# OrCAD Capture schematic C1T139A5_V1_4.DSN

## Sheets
1 00_Log: title: Telink-Semi; rev: V1.4; note: C1T139A5
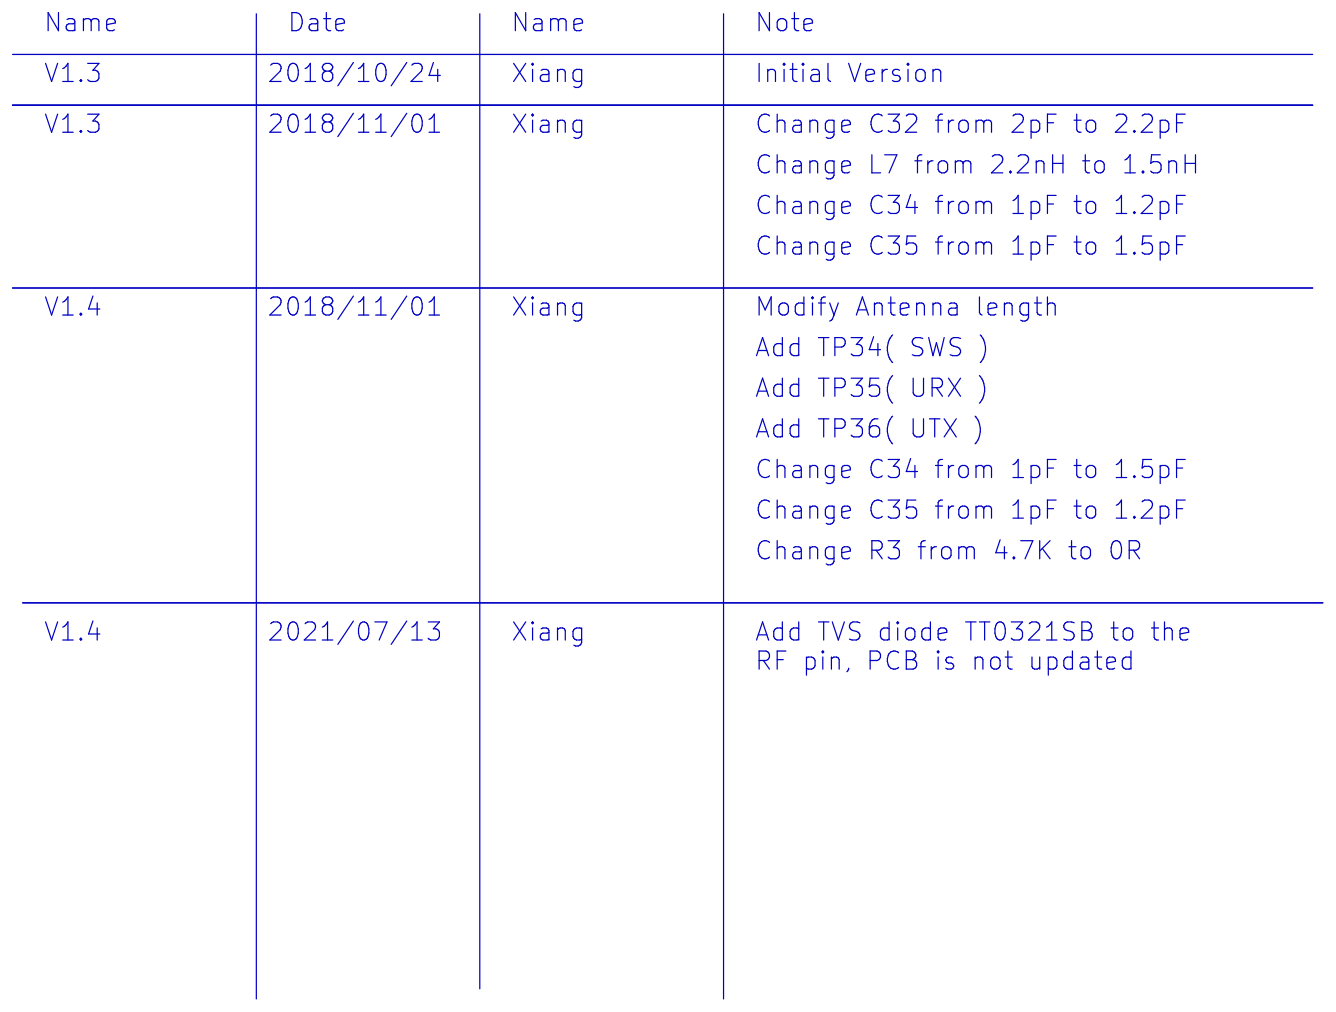
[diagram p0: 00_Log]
2 05_IR: size A4
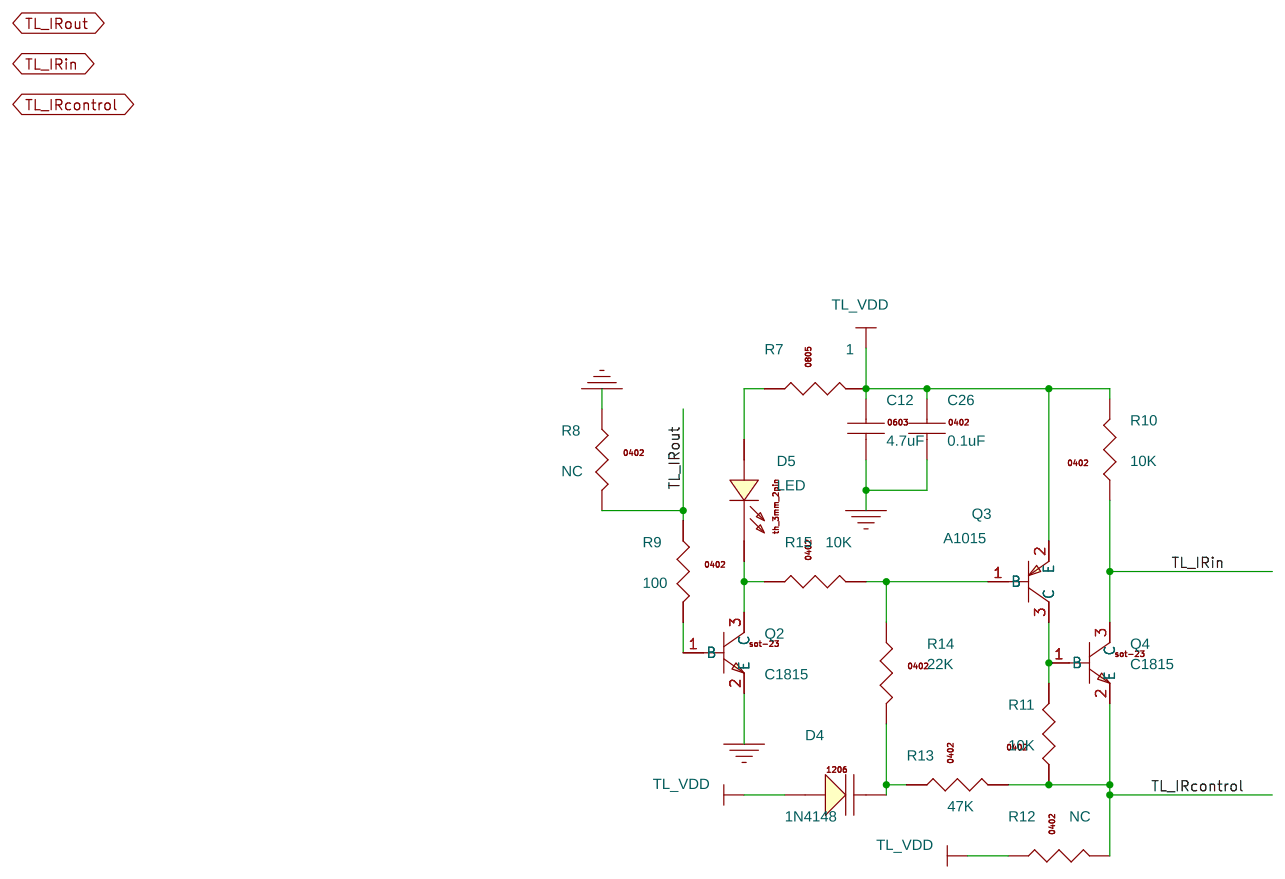
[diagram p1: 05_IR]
3 04_Audio: size A4
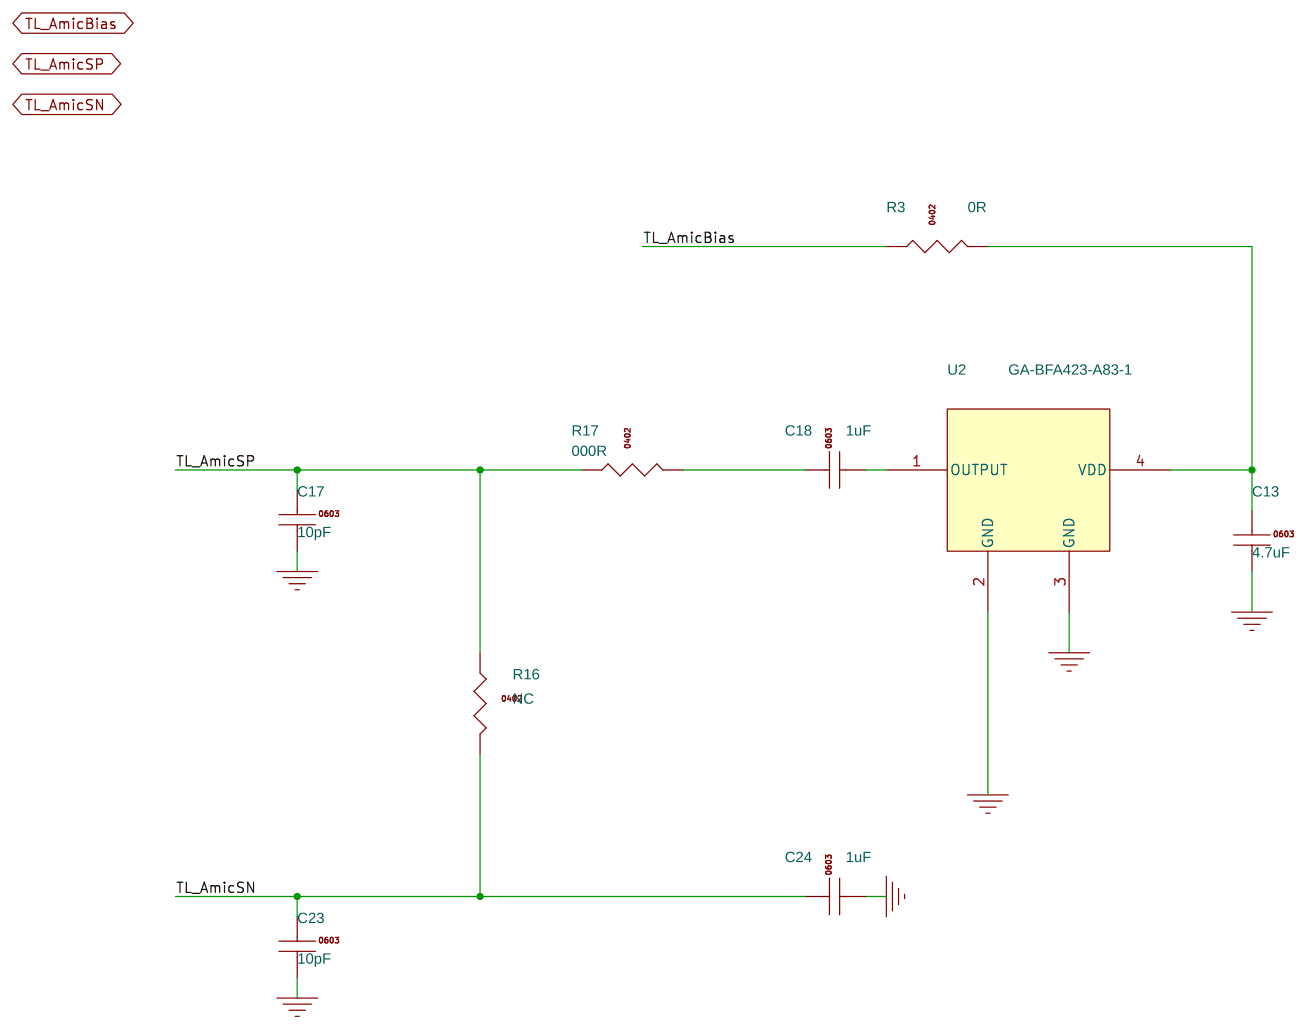
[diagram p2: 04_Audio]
4 01_CPU: size A4
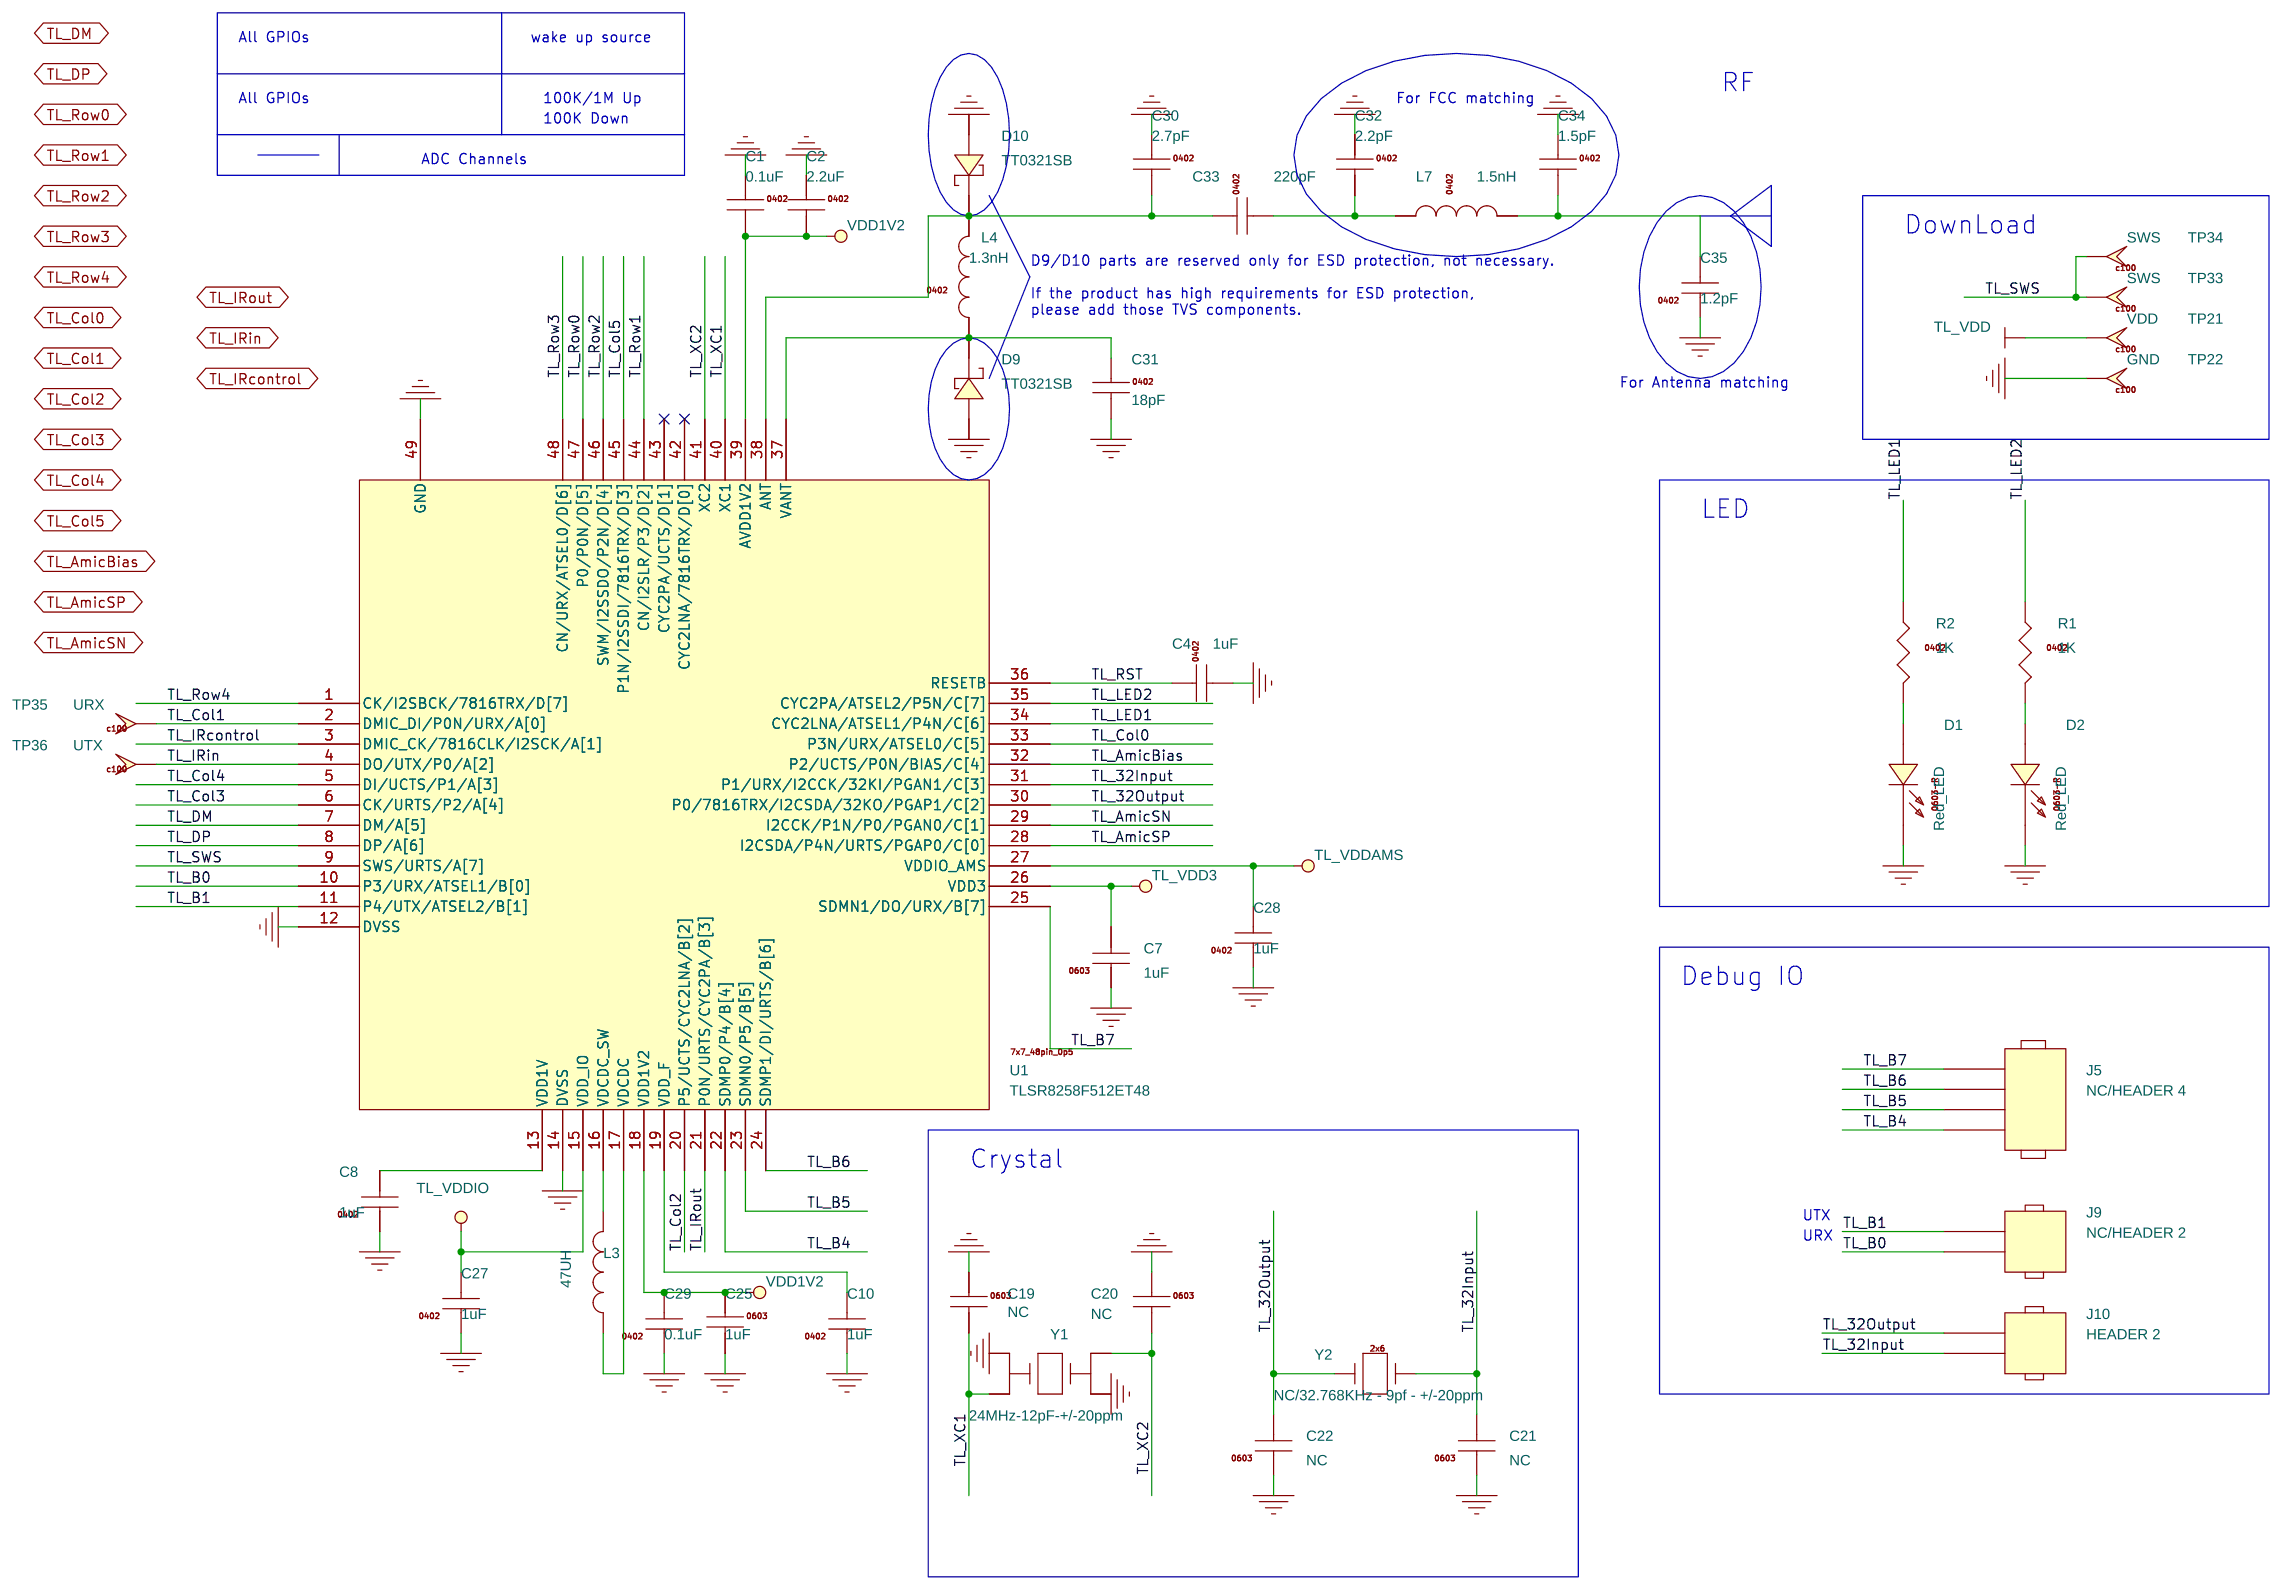
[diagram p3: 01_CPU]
5 02_Key: size A4
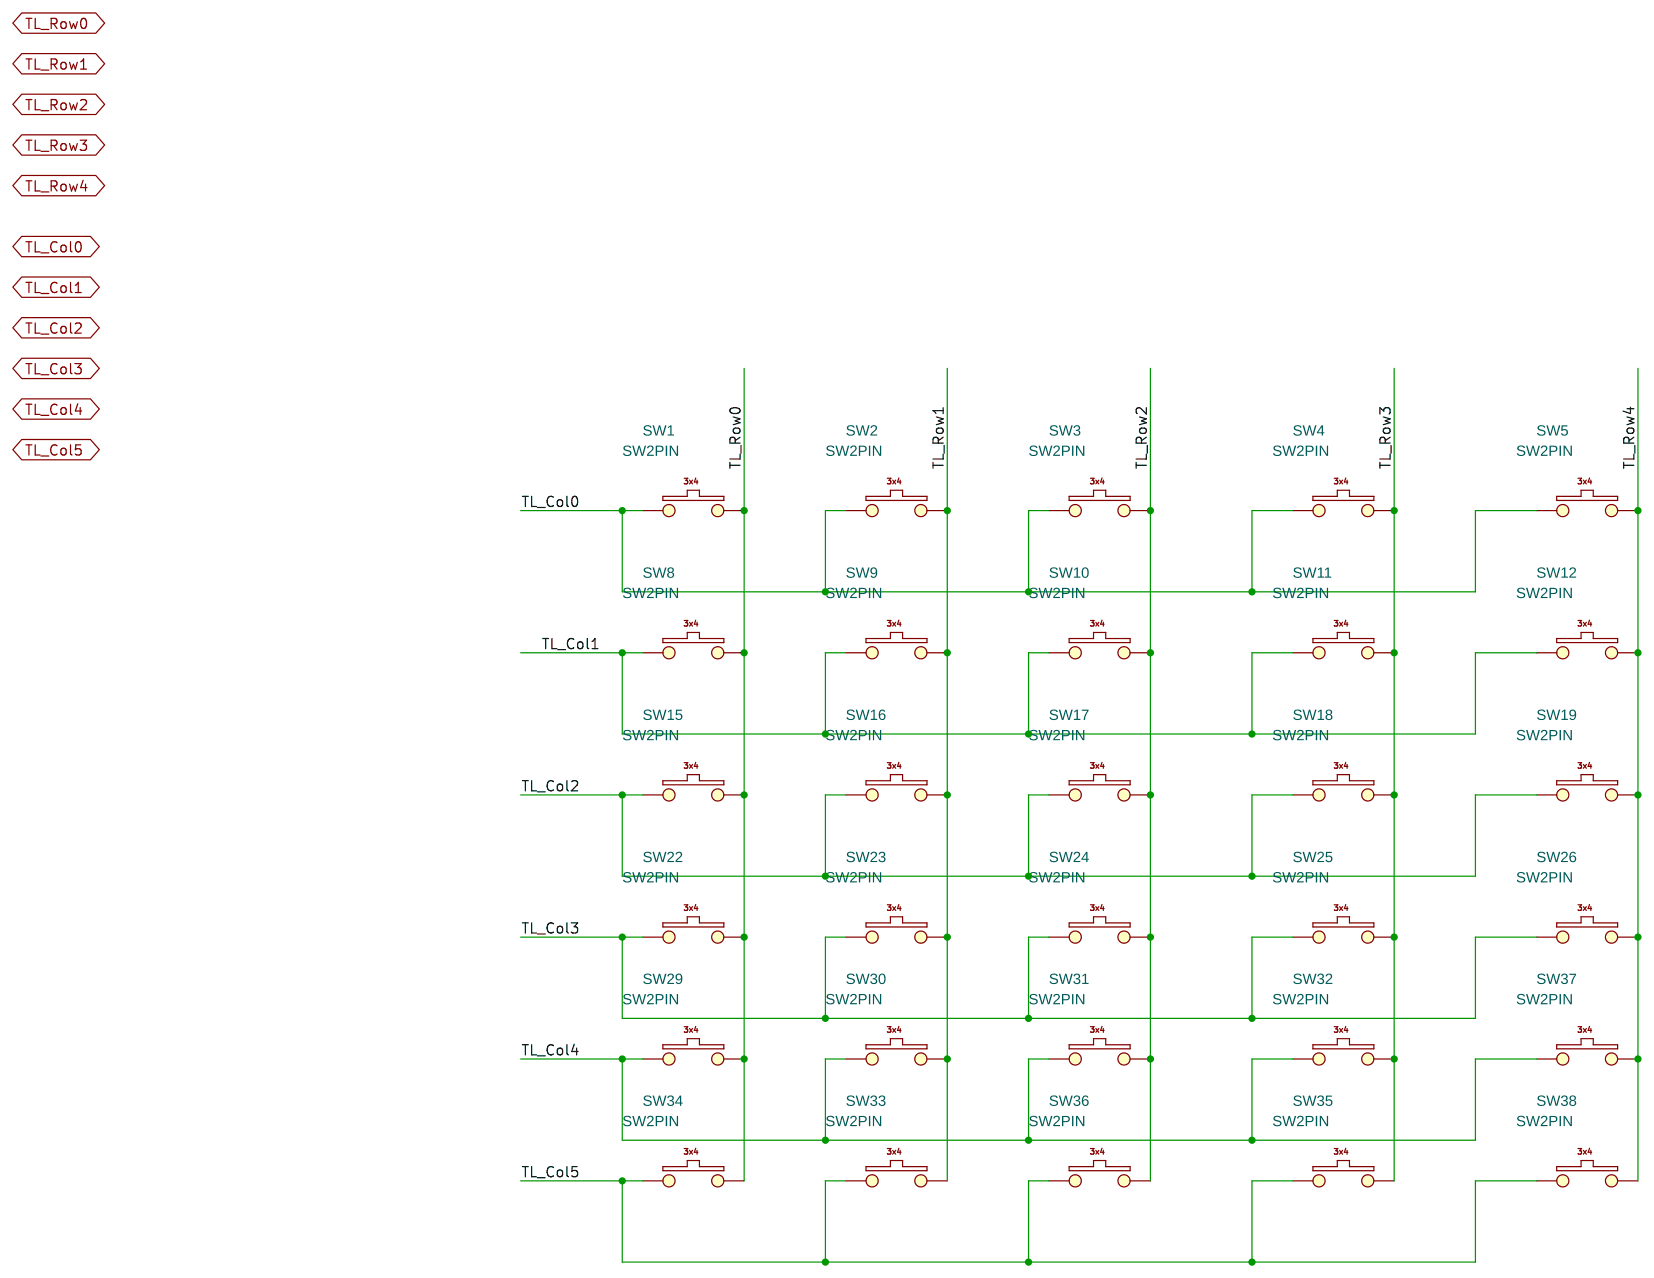
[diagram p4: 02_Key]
6 03_Power: size A4
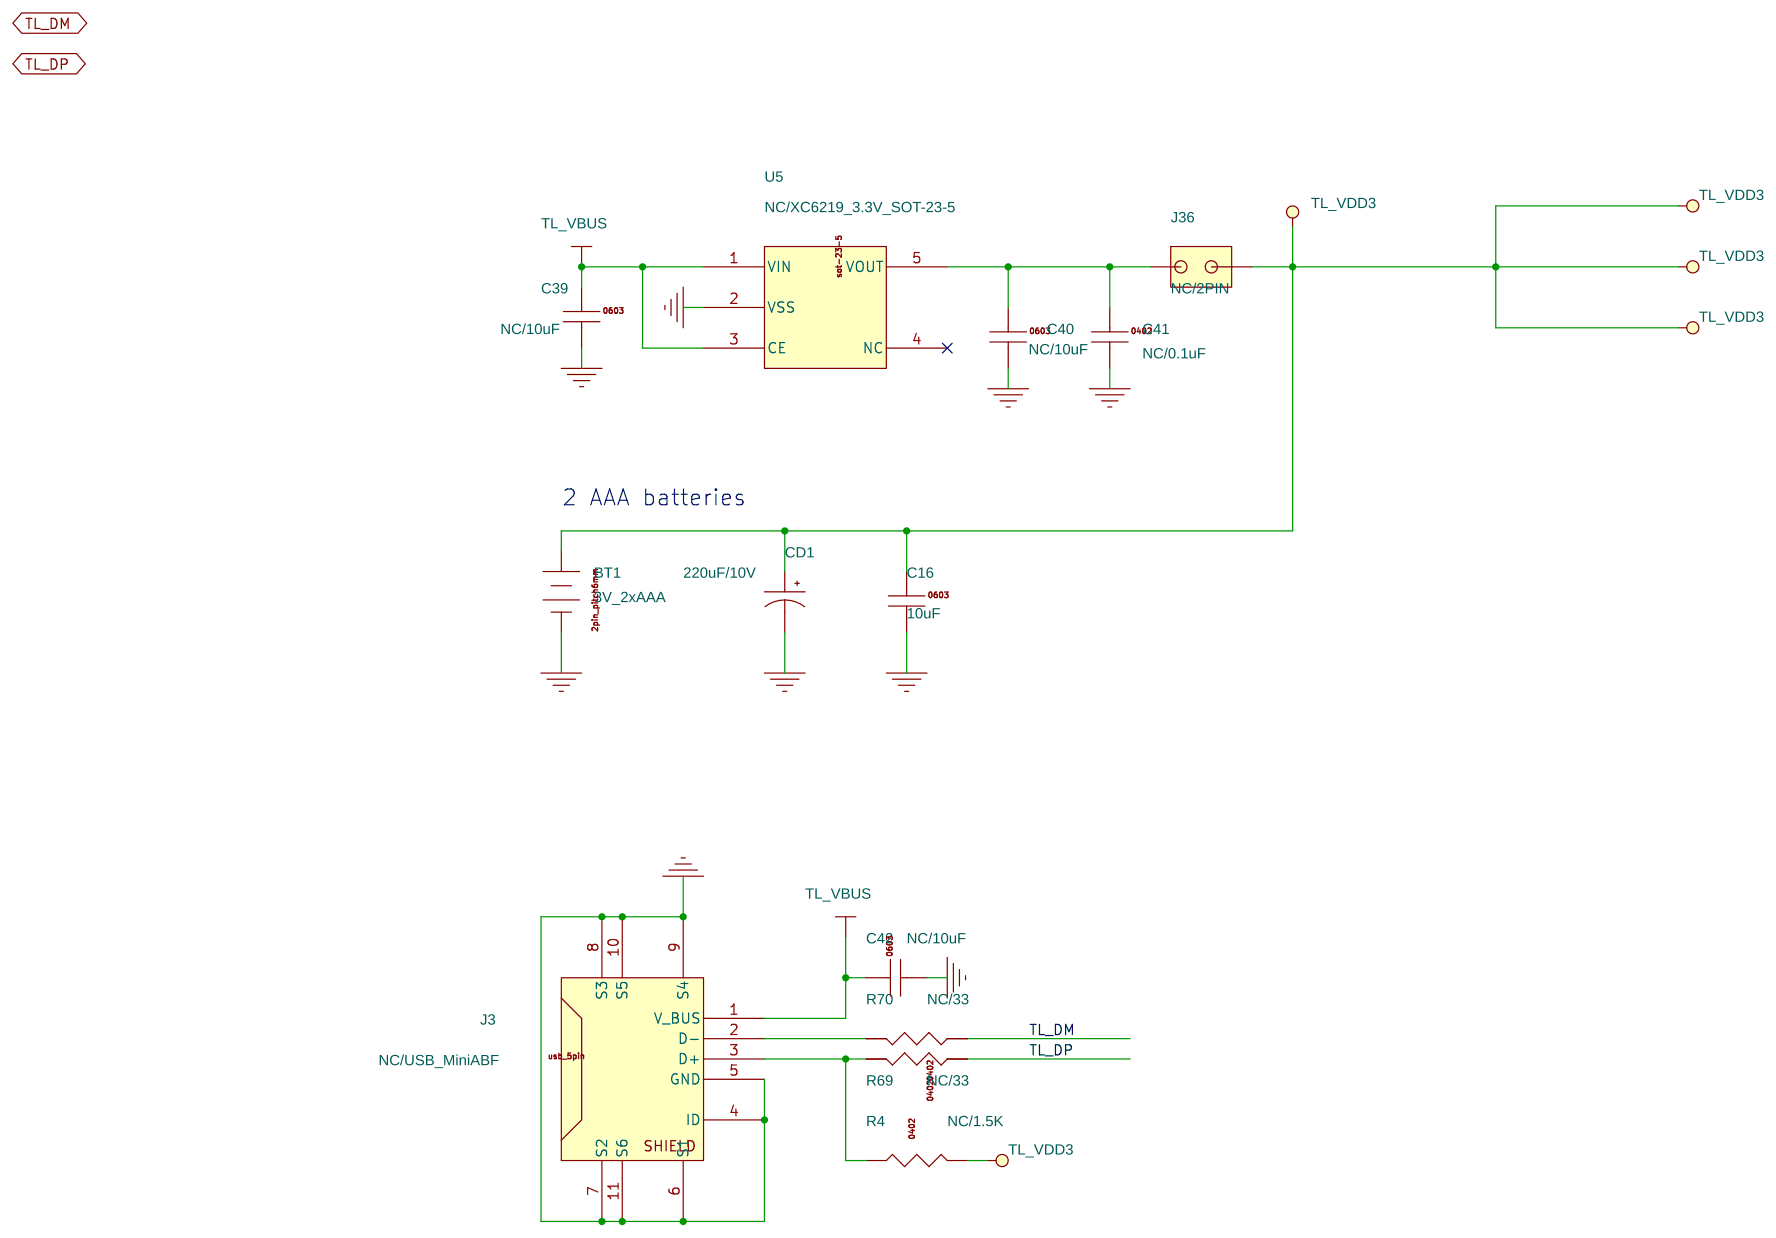
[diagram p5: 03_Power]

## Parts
sheet 01_CPU
C1  0.1uF  [0402]
C2  2.2uF  [0402]
C4  1uF  [0402]
C7  1uF  [0402]
C8  1uF  [0402]
C10  1uF  [0402]
C19  NC  [0402]
C20  NC  [0402]
C21  NC  [0402]
C22  NC  [0402]
C25  1uF  [0402]
C27  1uF  [0402]
C28  1uF  [0402]
C29  0.1uF  [0402]
C30  2.7pF  [0402C]
C31  18pF  [0402]
C32  2.2pF  [0402C]
C33  220pF  [0402C]
C34  1.5pF  [0402C]
C35  1.2pF  [0402]
D1  Red_LED  [0603-LED]
D2  Red_LED  [0603-LED]
D9  TT0321SB  [SOD-123]
D10  TT0321SB  [SOD-123]
J5  NC/HEADER 4  [hdr254f-1x4x850]
J9  NC/HEADER 2  [hdr254f-1x2x850]
J10  HEADER 2  [hdr254f-1x2x850]
L3  47UH  [0805L]
L4  1.3nH  [0402C]
L7  1.5nH  [0402C]
R1  1K  [0402]
R2  1K  [0402]
TP21  VDD  [tp100]
TP22  GND  [tp100]
TP33  SWS  [tp100]
TP34  SWS  [tp100]
TP35  URX  [tp100]
TP36  UTX  [tp100]
U1  TLSR8258F512ET48  [qfn_7x7_48pin_0p5_4p20x4p20]
Y1  24MHz-12pF-+/-20ppm  [osccc250x320x110]
Y2  NC/32.768KHz - 9pf - +/-20ppm  [OSC_2x6]
sheet 02_Key
SW1  SW2PIN  [sw_out6_in3]
SW2  SW2PIN  [sw_out6_in3]
SW3  SW2PIN  [sw_out6_in3]
SW4  SW2PIN  [sw_out6_in3]
SW5  SW2PIN  [sw_out6_in3]
SW8  SW2PIN  [sw_out6_in3]
SW9  SW2PIN  [sw_out6_in3]
SW10  SW2PIN  [sw_out6_in3]
SW11  SW2PIN  [sw_out6_in3]
SW12  SW2PIN  [sw_out6_in3]
SW15  SW2PIN  [sw_out6_in3]
SW16  SW2PIN  [sw_out6_in3]
SW17  SW2PIN  [sw_out6_in3]
SW18  SW2PIN  [sw_out6_in3]
SW19  SW2PIN  [sw_out6_in3]
SW22  SW2PIN  [sw_out6_in3]
SW23  SW2PIN  [sw_out6_in3]
SW24  SW2PIN  [sw_out6_in3]
SW25  SW2PIN  [sw_out6_in3]
SW26  SW2PIN  [sw_out6_in3]
SW29  SW2PIN  [sw_out6_in3]
SW30  SW2PIN  [sw_out6_in3]
SW31  SW2PIN  [sw_out6_in3]
SW32  SW2PIN  [sw_out6_in3]
SW33  SW2PIN  [sw_out6_in3]
SW34  SW2PIN  [sw_out6_in3]
SW35  SW2PIN  [sw_out6_in3]
SW36  SW2PIN  [sw_out6_in3]
SW37  SW2PIN  [sw_out6_in3]
SW38  SW2PIN  [sw_out6_in3]
sheet 03_Power
BT1  3V_2xAAA  [bat_2dip]
C16  10uF  [0603c]
C39  NC/10uF  [0603c]
C40  NC/10uF  [0603c]
C41  NC/0.1uF  [0402]
C42  NC/10uF  [0603c]
CD1  220uF/10V  [cd2p0_4p0b]
J3  NC/USB_MiniABF  [microusb_dip]
J36  NC/2PIN  [HDR254F-1X2X850]
R4  NC/1.5K  [0402]
R69  NC/33  [0402]
R70  NC/33  [0402]
U5  NC/XC6219_3.3V_SOT-23-5  [sot-23-5]
sheet 04_Audio
C13  4.7uF  [0402]
C17  10pF  [0402]
C18  1uF  [0402]
C23  10pF  [0402]
C24  1uF  [0402]
R3  0R  [0402]
R16  NC  [0402]
R17  000R  [0402]
U2  GA-BFA423-A83-1  [ga_bfa423_a83]
sheet 05_IR
C12  4.7uF  [0402]
C26  0.1uF  [0402]
D4  1N4148  [SOD80]
D5  LED  [led_th_2p54mm_2pin]
Q2  C1815  [SOT-23]
Q3  A1015  [SOT-23]
Q4  C1815  [SOT-23]
R7  1  [0402]
R8  NC  [0402]
R9  100  [0402]
R10  10K  [0402]
R11  10K  [0402]
R12  NC  [0402]
R13  47K  [0402]
R14  22K  [0402]
R15  10K  [0402]

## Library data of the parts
C1 C26 C41 = C1005X5R1C104K
C2 = C1005X5R1A225K
C4 C8 = C1005X5R1C105K
C7 = C1608X5R1C105M_0
C10 = C1005X5R1C105K_0
C19-C22 = C1608_NC
C13 C17 C18 C23-C25 = C1608X5R0J475M
C27 C29 = C1005X5R1C105K_1
C28 = C1005X5R1C105K_2
C30 C32-C34 = C1608_NC_0
C31 = C1005C0G1H100D
C35 = C1005_NC
D1 D2 = 0603D_Red
D9 D10 = DIODE_SCHOTTKY_0
J5 = HEADER_4
J9 J10 = HEADER_2
L3 = IND_0
L4 L7 = MLK1608_0
R1-R4 R16 R17 = RS0402K472JT
TP21 TP22 TP33-TP36 = TestPad100
U1 = TLSR8258F512ET48
Y1 = CRYSTAL4_SM_0
Y2 = OSC_2x6_2pin_16Mhz
SW1-SW5 SW8-SW12 SW15-SW19 SW22-SW26 SW29-SW38 = SW2PIN_0
BT1 = BATTERY_2xAAA_3V
C16 = C1608X5R0J106M
C39 C40 C42 = C1608X5R1A106K
CD1 = CD_220uF_16V
J3 = USB_MiniABF_2
J36 = B2S_2: PAGE: POWER
R69 R70 = RS0402K330JT
U5 = XC6219_1.3V_SOT-23-5
U2 = MULPS4CX-RM5_0
C12 = C1608X5R1A226M
D4 = Diode_1N4148
D5 = Led_Th_3mm_1
Q2 Q4 = NPN_C1815
Q3 = PNP_A1015
R7 = RS0805K1R0JT
R8 R12 = RS0402_NC
R9 = RS0402K101JT
R10 R11 R15 = RS0402K103JT
R13 = RS0402K473JT
R14 = RS0402K223JT

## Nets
GND: BT1.2(-) C1.1 C2.1 C4.2 C7.1 C8.1 C10.1 C12.2 C13.2 C16.2 C17.2 C19.1 C20.1 C21.1 C22.1 C23.2 C24.2 C25.2 C26.2 C27.1 C28.1 C29.1 C30.1 C31.2 C32.1 C34.1 C35.1 C39.2 C40.2 C41.2 C42.2 CD1.2 D1.C(CATHODE) D2.C(CATHODE) D9.A(ANODE) D10.A(ANODE) J3.4(ID) J3.5(GND) J3.6(S1) J3.7(S2) J3.8(S3) J3.9(S4) J3.10(S5) J3.11(S6) Q2.2(E) R8.1 TP22.1(TP) U1.12(DVSS) U1.14(DVSS) U1.49(GND) U2.2(GND) U2.3(GND) U5.2(VSS) Y1.2 Y1.4
VDD1V2: C1.2 C2.2 C25.1 C29.2 U1.18(VDD1V2) U1.39(AVDD1V2)
TL_32Input: C21.2 J10.2 U1.31(P1/URX/I2CCK/32KI/PGAN1/C[3]) Y2.2
TL_32Output: C22.2 J10.1 U1.30(P0/7816TRX/I2CSDA/32KO/PGAP1/C[2]) Y2.1
TL_AmicBias: U1.32(P2/UCTS/P0N/BIAS/C[4])
TL_AmicBias (page 04_Audio): R3.1
TL_AmicSN: U1.29(I2CCK/P1N/P0/PGAN0/C[1])
TL_AmicSN (page 04_Audio): C23.1 C24.1 R16.2
TL_AmicSP: U1.28(I2CSDA/P4N/URTS/PGAP0/C[0])
TL_AmicSP (page 04_Audio): C17.1 R16.1 R17.1
TL_B0: J9.2 U1.10(P3/URX/ATSEL1/B[0])
TL_B1: J9.1 U1.11(P4/UTX/ATSEL2/B[1])
TL_B4: J5.1 U1.22(SDMP0/P4/B[4])
TL_B5: J5.2 U1.23(SDMN0/P5/B[5])
TL_B6: J5.3 U1.24(SDMP1/DI/URTS/B[6])
TL_B7: J5.4 U1.25(SDMN1/DO/URX/B[7])
TL_Col0: U1.33(P3N/URX/ATSEL0/C[5])
TL_Col0 (page 02_Key): SW1.1 SW2.1 SW3.1 SW4.1 SW5.1
TL_Col1: TP35.1(TP) U1.2(DMIC_DI/P0N/URX/A[0])
TL_Col1 (page 02_Key): SW8.1 SW9.1 SW10.1 SW11.1 SW12.1
TL_Col2: U1.20(P5/UCTS/CYC2LNA/B[2])
TL_Col2 (page 02_Key): SW15.1 SW16.1 SW17.1 SW18.1 SW19.1
TL_Col3: U1.6(CK/URTS/P2/A[4])
TL_Col3 (page 02_Key): SW22.1 SW23.1 SW24.1 SW25.1 SW26.1
TL_Col4: U1.5(DI/UCTS/P1/A[3])
TL_Col4 (page 02_Key): SW29.1 SW30.1 SW31.1 SW32.1 SW37.1
TL_Col5: U1.45(P1N/I2SSDI/7816TRX/D[3])
TL_Col5 (page 02_Key): SW33.1 SW34.1 SW35.1 SW36.1 SW38.1
TL_DM: U1.7(DM/A[5])
TL_DM (page 03_Power): R70.1
TL_DP: U1.8(DP/A[6])
TL_DP (page 03_Power): R69.1
TL_IRcontrol: U1.3(DMIC_CK/7816CLK/I2SCK/A[1])
TL_IRcontrol (page 05_IR): Q4.2(E) R11.1 R12.2 R13.2
TL_IRin: TP36.1(TP) U1.4(DO/UTX/P0/A[2])
TL_IRin (page 05_IR): Q4.3(C) R10.1
TL_IRout: U1.21(P0N/URTS/CYC2PA/B[3])
TL_IRout (page 05_IR): R8.2 R9.1
TL_LED1: R2.1 U1.34(CYC2LNA/ATSEL1/P4N/C[6])
TL_LED2: R1.1 U1.35(CYC2PA/ATSEL2/P5N/C[7])
TL_Row0: U1.47(P0/P0N/D[5])
TL_Row0 (page 02_Key): SW1.2 SW8.2 SW15.2 SW22.2 SW29.2 SW34.2
TL_Row1: U1.44(CN/I2SLR/P3/D[2])
TL_Row1 (page 02_Key): SW2.2 SW9.2 SW16.2 SW23.2 SW30.2 SW33.2
TL_Row2: U1.46(SWM/I2SSDO/P2N/D[4])
TL_Row2 (page 02_Key): SW3.2 SW10.2 SW17.2 SW24.2 SW31.2 SW36.2
TL_Row3: U1.48(CN/URX/ATSEL0/D[6])
TL_Row3 (page 02_Key): SW4.2 SW11.2 SW18.2 SW25.2 SW32.2 SW35.2
TL_Row4: U1.1(CK/I2SBCK/7816TRX/D[7])
TL_Row4 (page 02_Key): SW5.2 SW12.2 SW19.2 SW26.2 SW37.2 SW38.2
TL_RST: C4.1 U1.36(RESETB)
TL_SWS: TP33.1(TP) TP34.1(TP) U1.9(SWS/URTS/A[7])
TL_VBUS: C39.1 C42.1 J3.1(V_BUS) U5.1(VIN) U5.3(CE)
TL_VDD: BT1.1(+) C7.2 C12.1 C16.1 C26.1 C27.2 C28.2 CD1.1 D4.A J36.2 Q3.2(E) R4.2 R7.2 R10.2 R12.1 TP21.1(TP) U1.15(VDD_IO) U1.26(VDD3) U1.27(VDDIO_AMS)
TL_XC1: C19.2 U1.40(XC1) Y1.3
TL_XC2: C20.2 U1.41(XC2) Y1.1
N21000893: D2.A(ANODE) R1.2
N21007782: D1.A(ANODE) R2.2
N21036936: C13.1 R3.2 U2.4(VDD)
N21036981: C18.1 R17.2
N21036983: C18.2 U2.1(OUTPUT)
N21081547: C40.1 C41.1 J36.1 U5.5(VOUT)
N21081898: J3.3(D+) R4.1 R69.2
N21081900: J3.2(D-) R70.2
N21088560: C10.2 U1.19(VDD_F)
N21088582: L3.1 U1.17(VDCDC)
N21088586: L3.2 U1.16(VDCDC_SW)
N21088616: C8.2 U1.13(VDD1V)
N21092390: C31.1 D9.C(CATHODE) L4.1 U1.37(VANT)
N21092394: C30.2 C33.1 D10.C(CATHODE) L4.2 U1.38(ANT)
N21092398: C32.2 C33.2 L7.1
N21092424: C34.2 C35.2 L7.2
N21108187: D5.A(ANODE) R7.1
N21108227: D4.C R13.1 R14.2
N21108333: Q2.1(B) R9.2
N21108349: D5.C(CATHODE) Q2.3(C) R15.1
N21108369: Q3.3(C) Q4.1(B) R11.2
N21108379: Q3.1(B) R14.1 R15.2

Not connected (* = marked no-connect by the designer): U1 42(CYC2LNA/7816TRX/D[0])* 43(CYC2PA/UCTS/D[1])*; U5 4(NC)*

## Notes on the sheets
sheet 1
- Name
- Date
- Name
- Note
- V1.3
- 2018/10/24
- Xiang
- Initial Version
- V1.3
- 2018/11/01
- Xiang
- Change C32 from 2pF to 2.2pF
- Change L7 from 2.2nH to 1.5nH
- Change C34 from 1pF to 1.2pF
- Change C35 from 1pF to 1.5pF
- V1.4
- 2018/11/01
- Xiang
- Modify Antenna length
- Add TP34( SWS )
- Add TP35( URX )
- Add TP36( UTX )
- Change C34 from 1pF to 1.5pF
- Change C35 from 1pF to 1.2pF
- Change R3 from 4.7K to 0R
- V1.4
- 2021/07/13
- Xiang
- Add TVS diode TT0321SB to the
  RF pin, PCB is not updated
sheet 4
- All GPIOs
- wake up source
- All GPIOs
- 100K/1M Up
- For FCC matching
- RF
- 100K Down
- ADC Channels
- DownLoad
- D9/D10 parts are reserved only for ESD protection, not necessary.
  If the product has high requirements for ESD protection,
  please add those TVS components.
- For Antenna matching
- LED
- Debug IO
- Crystal
- UTX
- URX
sheet 6
- 2 AAA batteries
